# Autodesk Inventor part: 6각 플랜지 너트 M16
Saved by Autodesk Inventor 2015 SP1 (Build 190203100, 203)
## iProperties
Created: 2026-07
Part Number: 6각 플랜지 너트 M16
Material: 일반
Document SubType Name: Modeling
Designer: user
Density: 1 g/cm^3
Appearance: 기본값
Author: user
Author: jhkim
Creation Date: 2026-07-01
Sending System: Autodesk Inventor 2027
Preprocessor: ST-DEVELOPER v20.1
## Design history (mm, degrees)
node "6각 플랜지 너트 M161"
body "Solid1"
node "기준1"
